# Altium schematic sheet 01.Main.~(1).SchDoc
size A4; CheckedBy: 20170717; Author: 赵金生; CompanyName: 广州周立功单片机科技有限公司; DocumentNumber: 1; SheetNumber: 1; SheetTotal: 7; PageSetup: Record=PageOptions¦CenterHorizontal=True¦CenterVertical=True¦PrintScale=1.00¦XCorrection=1.00¦YCorrection=1.00¦PrintKind=0¦BorderSize=5000000¦LeftOffset=0¦BottomOffset=0¦Orientation=2¦PaperLength=1000¦PaperWidth=1000¦Scale=100¦PaperSource=7¦PrintQuality=600¦MediaType=1¦DitherType=10¦PaperKind=A4¦PrintScaleMode=1; DesignDate: 2016-12-29; CheckDate: 赵金生; SheetName: Main; SheetVersion: V1.01; SheetDescription: Main; productModel: AMS32K144-Core; productName: 开发套件
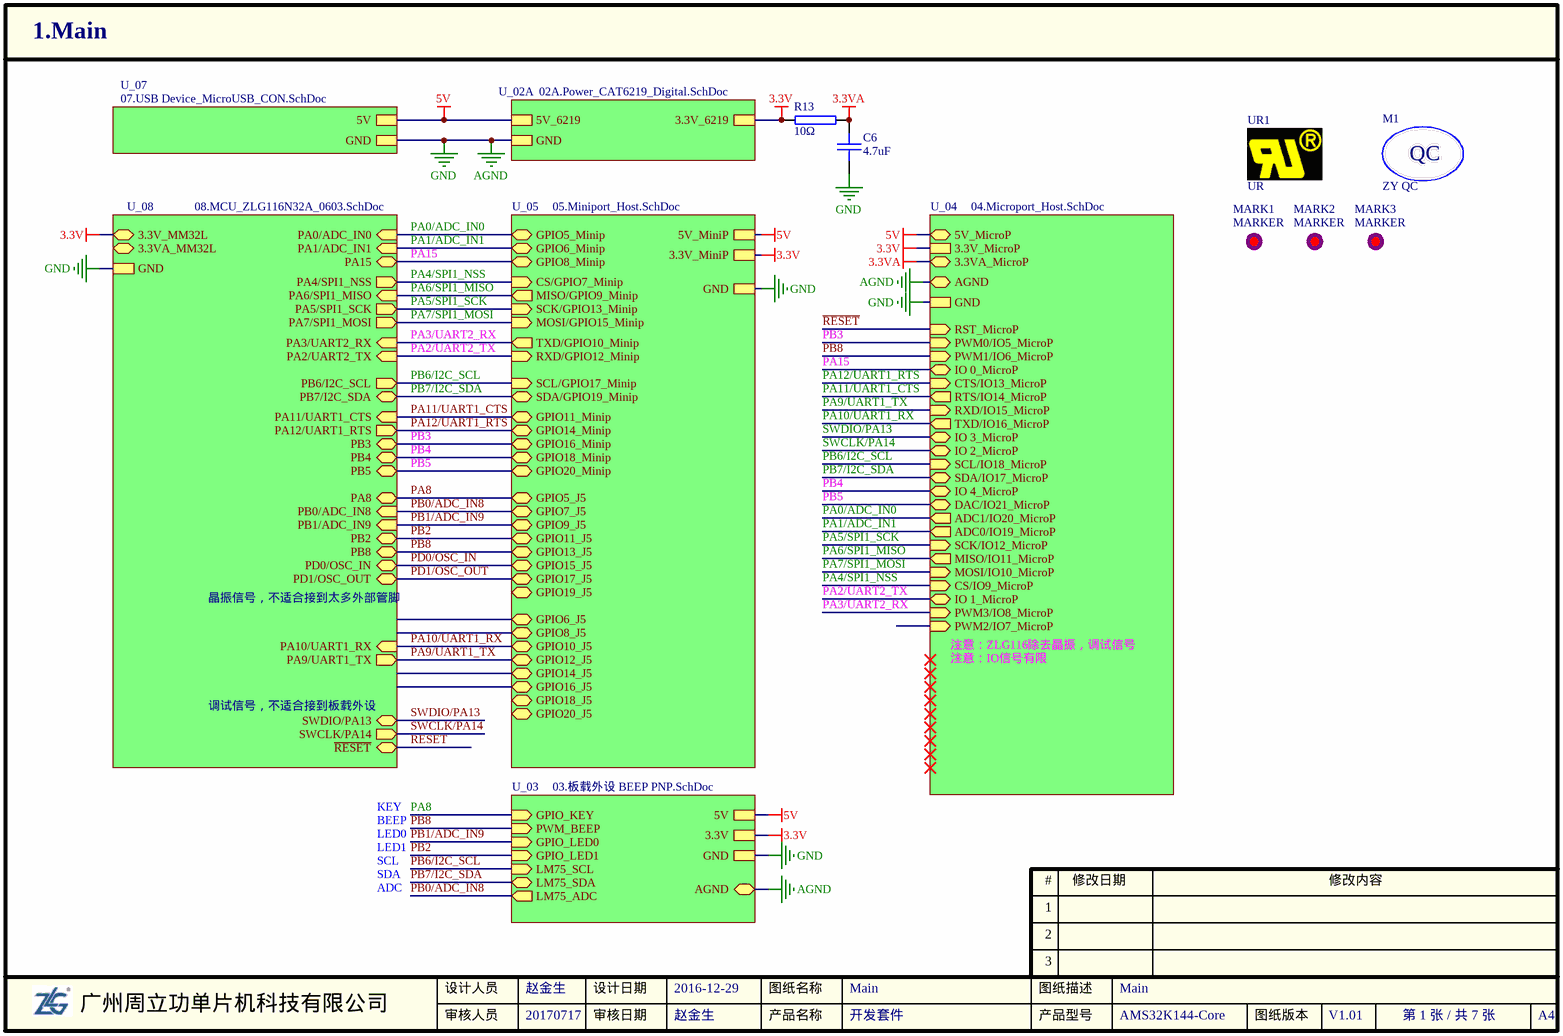
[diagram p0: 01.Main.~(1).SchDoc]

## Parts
C6  4.7uF  [0603C]
M1  ZY QC  [ZY_QC]  (no BOM)
MARK1  MARKER  [MARKER-C-1.0M]  (no BOM)
MARK2  MARKER  [MARKER-C-1.0M]  (no BOM)
MARK3  MARKER  [MARKER-C-1.0M]  (no BOM)
R13  10Ω  [0603R]
UR1  UR  [ZY_UR-3X2]  (no BOM)

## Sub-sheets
U_02A = 02A.Power_CAT6219_Digital.SchDoc: GND, 3.3V_6219, 5V_6219
U_03 = 03.板载外设 BEEP PNP.SchDoc: GND, 3.3V, PWM_BEEP (in), GPIO_LED0 (in), GPIO_LED1 (in), LM75_ADC (out), 5V, LM75_SCL (in), LM75_SDA (bidir), GPIO_KEY (in), AGND
U_04 = 04.Microport_Host.SchDoc: GND, 3.3V_MicroP, RXD/IO15_MicroP (in), TXD/IO16_MicroP (out), AGND, CTS/IO13_MicroP (in), MOSI/IO10_MicroP (in), SCK/IO12_MicroP (in), MISO/IO11_MicroP (out), IO 1_MicroP (bidir), IO 0_MicroP (bidir), IO 3_MicroP (bidir), IO 2_MicroP (bidir), IO 4_MicroP (bidir), PWM1/IO6_MicroP (in), PWM0/IO5_MicroP (in), PWM3/IO8_MicroP (in), PWM2/IO7_MicroP (in), SDA/IO17_MicroP (bidir), SCL/IO18_MicroP (in), ADC1/IO20_MicroP (out), ADC0/IO19_MicroP (out), DAC/IO21_MicroP (bidir), RST_MicroP (in), CS/IO9_MicroP (in), RTS/IO14_MicroP (out), 5V_MicroP, 3.3VA_MicroP
U_05 = 05.Miniport_Host.SchDoc: GND, 3.3V_MiniP, 5V_MiniP, MISO/GPIO9_Minip (out), GPIO5_Minip (bidir), GPIO8_Minip (bidir), SDA/GPIO19_Minip (bidir), SCL/GPIO17_Minip (in), GPIO16_Minip (bidir), GPIO18_Minip (bidir), MOSI/GPIO15_Minip (in), SCK/GPIO13_Minip (in), GPIO11_Minip (bidir), CS/GPIO7_Minip (in), GPIO20_Minip (bidir), GPIO14_Minip (bidir), GPIO6_Minip (bidir), RXD/GPIO12_Minip (in), TXD/GPIO10_Minip (out), GPIO5_J5 (bidir), GPIO6_J5 (bidir), GPIO8_J5 (bidir), GPIO11_J5 (bidir), GPIO14_J5 (bidir), GPIO16_J5 (bidir), GPIO18_J5 (bidir), GPIO20_J5 (bidir), GPIO9_J5 (bidir), GPIO10_J5 (bidir), GPIO12_J5 (bidir), GPIO7_J5 (bidir), GPIO13_J5 (bidir), GPIO15_J5 (bidir), GPIO17_J5 (bidir), GPIO19_J5 (bidir)
U_07 = 07.USB Device_MicroUSB_CON.SchDoc: 5V, GND
U_08 = 08.MCU_ZLG116N32A_0603.SchDoc: GND, PA15 (bidir), 3.3V_MM32L, SWCLK/PA14 (out), PB4 (bidir), PB3 (bidir), PA4/SPI1_NSS (out), PA0/ADC_IN0 (in), PA8 (bidir), PB2 (bidir), PA10/UART1_RX (in), PA1/ADC_IN1 (in), PB6/I2C_SCL (out), PB5 (bidir), PA11/UART1_CTS (in), PB7/I2C_SDA (bidir), PA6/SPI1_MISO (in), PA7/SPI1_MOSI (out), PB0/ADC_IN8 (in), PB1/ADC_IN9 (in), SWDIO/PA13 (bidir), PA12/UART1_RTS (out), PA9/UART1_TX (out), PA2/UART2_TX (in), PA3/UART2_RX (in), PA5/SPI1_SCK (out), PB8 (bidir), PD0/OSC_IN (bidir), PD1/OSC_OUT (bidir), ~{RESET} (bidir), 3.3VA_MM32L

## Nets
3.3V: R13.2 ; sheet U_02A/3.3V_6219, sheet U_05/3.3V_MiniP, sheet U_04/3.3V_MicroP, sheet U_03/3.3V, sheet U_08/3.3V_MM32L
3.3VA: C6.2 R13.1 ; sheet U_04/3.3VA_MicroP
5V: sheet U_02A/5V_6219, sheet U_07/5V, sheet U_05/5V_MiniP, sheet U_04/5V_MicroP, sheet U_03/5V
AGND: C6.1 ; sheet U_02A/GND, sheet U_07/GND, sheet U_05/GND, sheet U_04/GND, sheet U_04/AGND, sheet U_03/GND, sheet U_03/AGND, sheet U_08/GND  [also labelled GND]
PA0/ADC_IN0: sheet U_05/GPIO5_Minip, sheet U_04/ADC1/IO20_MicroP, sheet U_08/PA0/ADC_IN0
PA1/ADC_IN1: sheet U_05/GPIO6_Minip, sheet U_04/ADC0/IO19_MicroP, sheet U_08/PA1/ADC_IN1
PA2/UART2_TX: sheet U_05/RXD/GPIO12_Minip, sheet U_04/IO 1_MicroP, sheet U_08/PA2/UART2_TX
PA3/UART2_RX: sheet U_05/TXD/GPIO10_Minip, sheet U_04/PWM3/IO8_MicroP, sheet U_08/PA3/UART2_RX
PA4/SPI1_NSS: sheet U_05/CS/GPIO7_Minip, sheet U_04/CS/IO9_MicroP, sheet U_08/PA4/SPI1_NSS
PA5/SPI1_SCK: sheet U_05/SCK/GPIO13_Minip, sheet U_04/SCK/IO12_MicroP, sheet U_08/PA5/SPI1_SCK
PA6/SPI1_MISO: sheet U_05/MISO/GPIO9_Minip, sheet U_04/MISO/IO11_MicroP, sheet U_08/PA6/SPI1_MISO
PA7/SPI1_MOSI: sheet U_05/MOSI/GPIO15_Minip, sheet U_04/MOSI/IO10_MicroP, sheet U_08/PA7/SPI1_MOSI
PA8: sheet U_05/GPIO5_J5, sheet U_03/GPIO_KEY, sheet U_08/PA8
PA9/UART1_TX: sheet U_05/GPIO12_J5, sheet U_04/RXD/IO15_MicroP, sheet U_08/PA9/UART1_TX
PA10/UART1_RX: sheet U_05/GPIO10_J5, sheet U_04/TXD/IO16_MicroP, sheet U_08/PA10/UART1_RX
PA11/UART1_CTS: sheet U_05/GPIO11_Minip, sheet U_04/RTS/IO14_MicroP, sheet U_08/PA11/UART1_CTS
PA12/UART1_RTS: sheet U_05/GPIO14_Minip, sheet U_04/CTS/IO13_MicroP, sheet U_08/PA12/UART1_RTS
PA15: sheet U_05/GPIO8_Minip, sheet U_04/IO 0_MicroP, sheet U_08/PA15
PB0/ADC_IN8: sheet U_05/GPIO7_J5, sheet U_03/LM75_ADC, sheet U_08/PB0/ADC_IN8
PB1/ADC_IN9: sheet U_05/GPIO9_J5, sheet U_03/GPIO_LED0, sheet U_08/PB1/ADC_IN9
PB2: sheet U_05/GPIO11_J5, sheet U_03/GPIO_LED1, sheet U_08/PB2
PB3: sheet U_05/GPIO16_Minip, sheet U_04/PWM0/IO5_MicroP, sheet U_08/PB3
PB4: sheet U_05/GPIO18_Minip, sheet U_04/IO 4_MicroP, sheet U_08/PB4
PB5: sheet U_05/GPIO20_Minip, sheet U_04/DAC/IO21_MicroP, sheet U_08/PB5
PB6/I2C_SCL: sheet U_05/SCL/GPIO17_Minip, sheet U_04/SCL/IO18_MicroP, sheet U_03/LM75_SCL, sheet U_08/PB6/I2C_SCL
PB7/I2C_SDA: sheet U_05/SDA/GPIO19_Minip, sheet U_04/SDA/IO17_MicroP, sheet U_03/LM75_SDA, sheet U_08/PB7/I2C_SDA
PB8: sheet U_05/GPIO13_J5, sheet U_04/PWM1/IO6_MicroP, sheet U_03/PWM_BEEP, sheet U_08/PB8
PD0/OSC_IN: sheet U_05/GPIO15_J5, sheet U_08/PD0/OSC_IN
PD1/OSC_OUT: sheet U_05/GPIO17_J5, sheet U_08/PD1/OSC_OUT
~{RESET}: sheet U_04/RST_MicroP, sheet U_08/~{RESET}
SWCLK/PA14: sheet U_04/IO 2_MicroP, sheet U_08/SWCLK/PA14
SWDIO/PA13: sheet U_04/IO 3_MicroP, sheet U_08/SWDIO/PA13

Not connected (* = marked no-connect by the designer): MARK1 0; MARK2 0; MARK3 0

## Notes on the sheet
- 晶振信号，不适合接到太多外部管脚
- 注意：ZLG116除去晶振，调试信号
- 调试信号，不适合接到板载外设
- 注意：IO信号有限
- BEEP
- LED0
- LED1
- KEY
- SCL
- SDA
- ADC

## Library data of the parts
C6 = 1.02.01.0080: GRM188R61A475KE15D,4.7uF,±10%,10V,X5R,0603,muRata,RoHS; 名称: 电容; 封装: 0603; 贴片和直插: SMT; PCB备注: 160602yjh; 器件优选方案: 正常状态，可以选用
R13 = 1.01.01.0007: 10Ω,0603,*,RoHS; 名称: 电阻; 封装: 0603; 设备封装名称: R0603_10R; 厂商: Ralec; 贴片和直插: SMT; 器件优选方案: 正常状态，可以选用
